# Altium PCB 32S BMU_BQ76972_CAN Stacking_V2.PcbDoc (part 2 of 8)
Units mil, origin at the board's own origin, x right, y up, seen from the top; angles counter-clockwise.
Board outline 7319.29 x 5216.54 mil, 4 copper layers (Top Layer, Layer 1, Layer 2, Bottom Layer), stack 73.068 mil thick; 811 components, 524 nets, 2320 pads, 2669 vias.
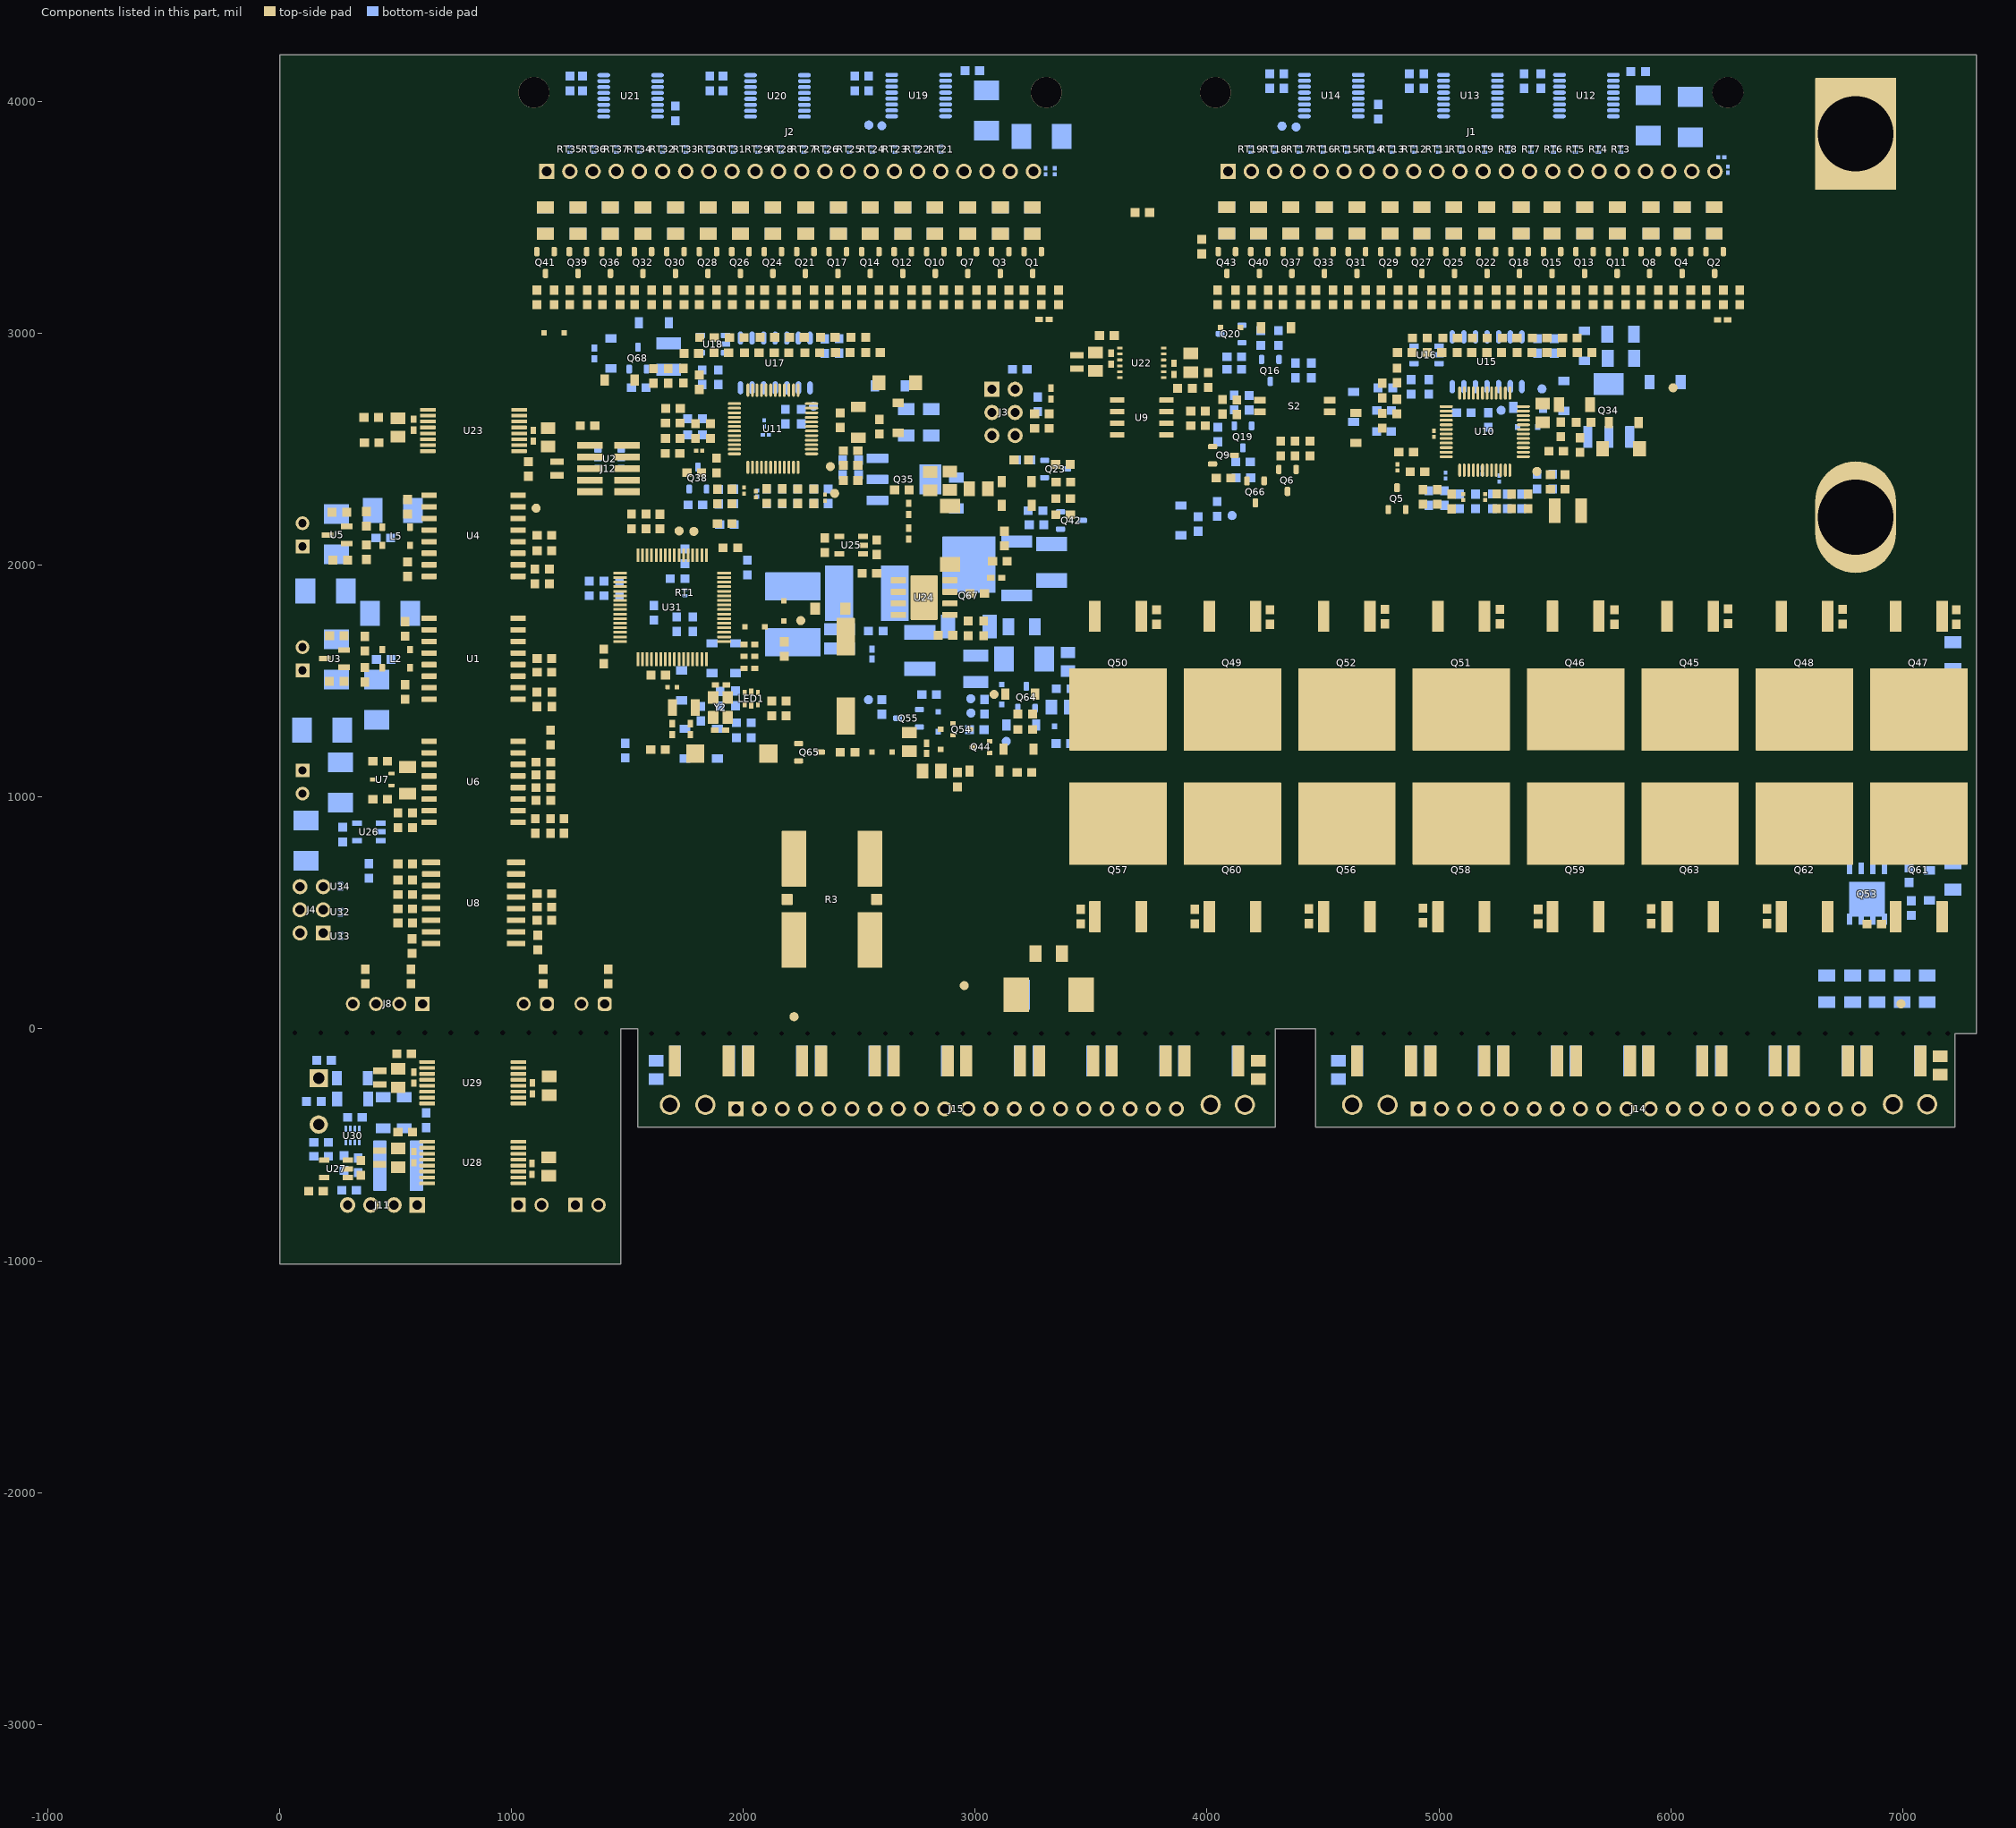
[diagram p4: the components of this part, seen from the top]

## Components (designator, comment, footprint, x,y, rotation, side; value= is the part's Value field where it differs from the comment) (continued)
R251 "CRCW0603100RFKEA" 0603 1695.4,2547.41 r0 top value=100
R252 "CRCW060310K0FKEA" 0603 2233.63,2298.04 r90 bottom value=10.0k
R253 "CRCW060310M0JNEA" 0603 3961.99,2178.07 r270 bottom value=10Meg
R254 "CRCW060310K0FKEA" 0603 1928.84,2175.36 r180 bottom value=10.0k
R255 "CRCW08051K50JNEA" 0805_HV 2812.37,1112.44 r0 top value=1.5k
R256 "CRCW06031M00JNEA" 0603 7027.93,663.39 r90 bottom value=1.0Meg
R257 "MCT06030C1004FP500" 0603 5107.86,2657.98 r0 bottom value=1.00Meg
R258 "RT0603BRD0749K9L" 0603 7037.77,521.14 r90 bottom value=49.9k
R259 "RC0603FR-07499RL" 0603 4044.23,2243.43 r270 bottom value=499
R260 "MCT06030C1004FP500" 0603 2249.69,2641.73 r90 bottom value=1.00Meg
R261 "CRCW0603806RFKEA" 0603 3215.59,1292.43 r180 top value=806
R262 "RC0603FR-07510RL" 0603 2597.25,1388.95 r270 bottom value=510
R263 "CRCW04020000Z0ED" 0603 3008.65,1878.64 r0 top value=0
R264 "CRCW04020000Z0ED" 0603 2683.68,2325.27 r180 top value=0
R265 "CRCW04020000Z0ED" 0603 394.83,2637.65 r180 top value=0
R266 "CRCW04020000Z0ED" 0603 384.71,681.15 r270 bottom value=0
R267 "CRCW04020000Z0ED" 0603 3904.87,2763.42 r0 top value=0
R268 "CRCW060375R0FKEA" 0603 4767.15,1778.76 r270 top value=75.0
R269 "CRCW060375R0FKEA" 0603 5915.35,486.14 r270 top value=75.0
R270 "CRCW060375R0FKEA" 0603 5262.84,1778.76 r270 top value=75.0
R271 "CRCW0603806RFKEA" 0603 2801.26,1442.73 r180 bottom value=806
R272 "CRCW080556K0JNEA" 0805_HV 2716.46,1238.36 r90 top value=56k
R273 "CRCW04020000Z0ED" 0603 3006.87,1290.78 r180 bottom value=0
R274 "CRCW080510R0FKEA" 0805_HV 3400.18,1583.79 r270 bottom value=10.0
R275 "CRCW0603806RFKEA" 0603 3040.45,1389.93 r90 bottom value=806
R276 "CRCW060375R0FKEA" 0603 6415.4,486.14 r270 top value=75.0
R277 "CRCW1206511RFKEA" 1206 6890.01,173.07 r270 bottom value=511
R278 "CRCW1206511RFKEA" 1206 7106.54,173.07 r270 bottom value=511
R279 "CRCW060375R0FKEA" 0603 3781.9,1776.95 r270 top value=75.0
R280 "CRCW060375R0FKEA" 0603 6878.09,452.83 r180 top value=75.0
R281 "CRCW060310M0JNEA" 0603 3380.2,1230.92 r180 bottom value=10Meg
R282 "CRCW060310M0JNEA" 0603 3381.89,1467.77 r180 bottom value=10Meg
R283 "CRCW080556K0JNEA" 0805_HV 3368.11,1388.43 r0 bottom value=56k
R284 "CRCW1206511RFKEA" 1206 6998.28,173.07 r270 bottom value=511
R285 "CRCW1206511RFKEA" 1206 6784.57,173.07 r270 bottom value=511
R286 "CRCW1206511RFKEA" 1206 6673.47,173.07 r270 bottom value=511
R287 "CRCW060375R0FKEA" 0603 4271.89,1776.95 r270 top value=75.0
R288 "CRCW060375R0FKEA" 0603 3946.85,484.33 r270 top value=75.0
R289 "CRCW060375R0FKEA" 0603 6742.13,1778.27 r270 top value=75.0
R290 "CRCW060375R0FKEA" 0603 5428.59,484.33 r270 top value=75.0
R291 "CRCW060375R0FKEA" 0603 7231.5,1776.95 r270 top value=75.0
R292 "CRCW0603100RFKEA" 0603 2449.45,1193.85 r0 top value=100
R293 "RC0603FR-0720RL" 0603 2176.72,1638.46 r270 top value=20.0
R294 "CRCW060310M0JNEA" 0603 2122.27,1382.74 r90 top value=10Meg
R295 "CRCW04020000Z0ED" 0603 1706.98,3949.41 r90 bottom value=0
R296 "CRCW04020000Z0ED" 0603 4737.95,3956.69 r90 bottom value=0
R297 "CRCW060310M0JNEA" 0603 1793.08,2260.63 r0 bottom value=10Meg
R298 "CRCW04020000Z0ED" 0603 2181,2641.73 r90 bottom value=0
R299 "CRCW06035K10JNEA" 0603 1966.1,1426 r270 bottom value=5.1k
R300 "RC0603FR-07604KL" 0603 2001.98,1320.58 r0 bottom value=604k
R301 "CRCW04020000Z0ED" 0603 5213,2626.49 r90 bottom value=0
R302 "RC0603FR-07620KL" 0603 1899.4,1424.64 r270 bottom value=620k
R303 "CRCW060310M0JNEA" 0603 3212.44,1106.53 r0 top value=10Meg
R304 "CRCW060310M0JNEA" 0603 3215.59,1358.27 r0 top value=10Meg
R305 "CRCW0603100RFKEA" 0603 1328.1,2601.68 r0 top value=100
R306 "CRCW06035K10JNEA" 0603 1816.22,1360.22 r270 bottom value=5.1k
R307 "CRCW06035K10JNEA" 0603 2001.98,1256.53 r0 bottom value=5.1k
R308 "CRM2512-FX-2000ELF" 2512 3179.09,1985.78 r90 bottom value=200
R309 "RC1206FR-0720KL" 1206 3200.19,1735.24 r180 bottom value=20.0k
R310 "CRCW060318K2FKEA" 0603 1072.66,2415.93 r90 top value=18.2k
R311 "CRCW060318K2FKEA" 0603 3567.95,2991.26 r0 top value=18.2k
R312 "CRCW060375R0FKEA" 0603 4931.1,489.33 r270 top value=75.0
R313 "CRCW060375R0FKEA" 0603 5757.22,1776.95 r270 top value=75.0
R314 "CRCW060375R0FKEA" 0603 3454.88,484.33 r270 top value=75.0
R315 "CRCW04020000Z0ED" 0603 191.22,-135.3 r0 bottom value=0
R316 "CRCW060375R0FKEA" 0603 6247.93,1780.08 r270 top value=75.0
R317 "RC0603FR-07499KL" 0603 3106.22,2018.01 r180 top value=499k
R318 "CRCW04020000Z0ED" 0603 338.47,-588.05 r270 bottom value=0
R319 "CRCW04020000Z0ED" 0603 147.11,-312.46 r0 bottom value=0
R320 "CRCW0402523KFKED" 0402 2713.67,2136.82 r90 top value=523k
R321 "CRCW060375R0FKEA" 0603 4438.98,486.14 r270 top value=75.0
R322 "CRCW060318K2FKEA" 0603 541.48,-444.84 r0 top value=18.2k
R323 "CRCW060318K2FKEA" 0603 536.9,-107.1 r0 top value=18.2k
R324 "CRCW0603200KFKEA" 0603 3036.59,1728.11 r90 top value=200k
R325 "CRCW060382K5FKEA" 0603 2571.25,1716.54 r180 bottom value=82.5k
R326 "RC0603FR-0710K2L" 0603 178.6,-489.24 r0 bottom value=10.2k
R327 "RC0603FR-0753K6L" 0603 178.6,-548.68 r0 bottom value=53.6k
R328 "CRCW060363K4FKEA" 0603 2871.53,1698 r0 top value=63.4k
R329 "CRCW060310K0FKEA" 0603 2923.23,1075.04 r90 top value=10.0k
R330 "RT0603BRD0718KL" 0603 2987.63,4133.51 r0 bottom value=18.0k
R331 "CRCW2512200RFKEG" 2512 4764.51,-137.67 r180 bottom value=200
R332 "CRCW2512200RFKEG" 2512 4763.1,-137.67 r180 top value=200
R333 "CRCW2512200RFKEG" 2512 5078.06,-137.67 r180 bottom value=200
R334 "CRCW2512200RFKEG" 2512 5080.3,-137.67 r180 top value=200
R335 "CRCW2512200RFKEG" 2512 5391.62,-137.67 r180 bottom value=200
R336 "CRCW2512200RFKEG" 2512 5394.68,-137.67 r180 top value=200
R337 "CRCW2512200RFKEG" 2512 5705.17,-137.67 r180 bottom value=200
R338 "CRCW2512200RFKEG" 2512 5708.44,-137.67 r180 top value=200
R339 "CRCW2512200RFKEG" 2512 6018.72,-137.67 r180 bottom value=200
R340 "CRCW2512200RFKEG" 2512 6020.32,-137.67 r180 top value=200
R341 "CRCW2512200RFKEG" 2512 6332.28,-137.67 r180 bottom value=200
R342 "CRCW2512200RFKEG" 2512 6335.48,-137.67 r180 top value=200
R343 "CRCW2512200RFKEG" 2512 6645.83,-137.67 r180 bottom value=200
R344 "CRCW2512200RFKEG" 2512 6648.16,-137.67 r180 top value=200
R345 "CRCW2512200RFKEG" 2512 6959.39,-137.67 r180 bottom value=200
R346 "CRCW2512200RFKEG" 2512 6961.57,-137.67 r180 top value=200
R347 "CRCW080510R0FKEA" 0805_HV 4566.78,-177.03 r270 bottom value=10.0
R348 "CRCW080510R0FKEA" 0805_HV 7162.65,-157.32 r270 top value=10.0
R349 "CRCW2512200RFKEG" 2512 1821.74,-137.66 r180 bottom value=200
R350 "CRCW2512200RFKEG" 2512 1820.33,-137.66 r180 top value=200
R351 "CRCW2512200RFKEG" 2512 2135.3,-137.66 r180 bottom value=200
R352 "CRCW2512200RFKEG" 2512 2137.53,-137.66 r180 top value=200
R353 "CRCW2512200RFKEG" 2512 2448.85,-137.66 r180 bottom value=200
R354 "CRCW2512200RFKEG" 2512 2451.92,-137.66 r180 top value=200
R355 "CRCW2512200RFKEG" 2512 2762.41,-137.66 r180 bottom value=200
R356 "CRCW2512200RFKEG" 2512 2765.67,-137.67 r180 top value=200
R357 "CRCW2512200RFKEG" 2512 3075.96,-137.66 r180 bottom value=200
R358 "CRCW2512200RFKEG" 2512 3077.55,-137.67 r180 top value=200
R359 "CRCW2512200RFKEG" 2512 3389.51,-137.66 r180 bottom value=200
R360 "CRCW2512200RFKEG" 2512 3392.71,-137.67 r180 top value=200
R361 "CRCW2512200RFKEG" 2512 3703.07,-137.66 r180 bottom value=200
R362 "CRCW2512200RFKEG" 2512 3705.39,-137.67 r180 top value=200
R363 "CRCW2512200RFKEG" 2512 4016.62,-137.66 r180 bottom value=200
R364 "CRCW2512200RFKEG" 2512 4018.8,-137.67 r180 top value=200
R365 "CRCW080510R0FKEA" 0805_HV 1624.02,-177.03 r270 bottom value=10.0
R366 "CRCW080510R0FKEA" 0805_HV 4221.47,-177.03 r270 top value=10.0
RT1 "TMP6131DECR" DEC0002A 1747.87,1882.35 r90 bottom
RT3 "TMP6131DECR" DEC0002A 5784.71,3794.29 r90 bottom
RT4 "TMP6131DECR" DEC0002A 5687.79,3794.29 r90 bottom
RT5 "TMP6131DECR" DEC0002A 5588.75,3794.29 r90 bottom
RT6 "TMP6131DECR" DEC0002A 5494.58,3794.29 r90 bottom
RT7 "TMP6131DECR" DEC0002A 5397.64,3794.29 r90 bottom
RT8 "TMP6131DECR" DEC0002A 5297.64,3794.29 r90 bottom
RT9 "TMP6131DECR" DEC0002A 5197.64,3794.29 r90 bottom
RT10 "TMP6131DECR" DEC0002A 5097.07,3794.29 r90 bottom
RT11 "TMP6131DECR" DEC0002A 4997.64,3794.29 r90 bottom
RT12 "TMP6131DECR" DEC0002A 4894.04,3794.29 r90 bottom
RT13 "TMP6131DECR" DEC0002A 4797.64,3794.29 r90 bottom
RT14 "TMP6131DECR" DEC0002A 4706.95,3794.29 r90 bottom
RT15 "TMP6131DECR" DEC0002A 4603.33,3794.29 r90 bottom
RT16 "TMP6131DECR" DEC0002A 4499.71,3794.29 r90 bottom
RT17 "TMP6131DECR" DEC0002A 4396.09,3794.29 r90 bottom
RT18 "TMP6131DECR" DEC0002A 4292.46,3794.29 r90 bottom
RT19 "TMP6131DECR" DEC0002A 4188.84,3794.29 r90 bottom
RT21 "TMP6131DECR" DEC0002A 2852.05,3794.66 r90 bottom
RT22 "TMP6131DECR" DEC0002A 2751.62,3794.29 r90 bottom
RT23 "TMP6131DECR" DEC0002A 2653.94,3794.29 r90 bottom
RT24 "TMP6131DECR" DEC0002A 2555.91,3794.29 r90 bottom
RT25 "TMP6131DECR" DEC0002A 2457.49,3794.29 r90 bottom
RT26 "TMP6131DECR" DEC0002A 2359.06,3794.29 r90 bottom
RT27 "TMP6131DECR" DEC0002A 2260.63,3794.29 r90 bottom
RT28 "TMP6131DECR" DEC0002A 2162.42,3794.29 r90 bottom
RT29 "TMP6131DECR" DEC0002A 2062.29,3794.29 r90 bottom
RT30 "TMP6131DECR" DEC0002A 1857.09,3794.29 r90 bottom
RT31 "TMP6131DECR" DEC0002A 1955.52,3794.29 r90 bottom
RT32 "TMP6131DECR" DEC0002A 1651.43,3794.29 r90 bottom
RT33 "TMP6131DECR" DEC0002A 1751.43,3794.29 r90 bottom
RT34 "TMP6131DECR" DEC0002A 1551.97,3794.29 r90 bottom
RT35 "TMP6131DECR" DEC0002A 1251.43,3794.29 r90 bottom
RT36 "TMP6131DECR" DEC0002A 1355.12,3794.29 r90 bottom
RT37 "TMP6131DECR" DEC0002A 1452.64,3794.29 r90 bottom
S1 "RS-032G05A3-SM RT" SW_RS-032G05A3-SM 1950.18,1187.94 r180 top
S2 "416131160802" SW_416131160802 4378.39,2687.15 r0 top
TP1 "" TP_SM_1MM 2597.27,3895.98 r90 bottom
TP2 "" TP_SM_1MM 6010.32,2765.51 r90 top
TP3 "" TP_SM_1MM 1722.95,2148.31 r90 top
TP4 "" TP_SM_1MM 1106.07,2246.34 r90 top
TP5 "" TP_SM_1MM 6993.21,108.27 r90 top
TP6 "" TP_SM_1MM 2952.76,187.01 r90 top
TP7 "" TP_SM_1MM 4107.9,2214.69 r90 bottom
TP8 "" TP_SM_1MM 1786.34,2146.12 r90 top
TP9 "I-" Keystone5009 4779.08,-327.36 r180 top
TP10 "" TP_SM_1MM 2980.84,1424.5 r90 bottom
TP11 "" TP_SM_1MM 2981.8,1362.7 r90 bottom
TP12 "I-" Keystone5009 6958.59,-324.8 r180 top
TP13 "" TP_SM_1MM 2247.37,1761.57 r90 top
TP14 "" TP_SM_1MM 2218.5,52.75 r90 top
TP15 "" TP_SM_1MM 2540.79,3899.06 r90 bottom
TP16 "" TP_SM_1MM 4323.5,3894.63 r90 bottom
TP17 "BAT-" Keystone5011 4625.84,-327.36 r270 top
TP18 "" TP_SM_1MM 4384.07,3890.72 r90 bottom
TP21 "" TP_SM_1MM 2302.43,2686.17 r90 bottom
TP22 "" TP_SM_1MM 5268.67,2668.29 r90 bottom
TP23 "" TP_SM_1MM 2375.35,2426.02 r90 top
TP24 "BAT+" Keystone5010 7106.54,-324.8 r180 top
TP25 "I-" Keystone5009 1836.32,-327.35 r180 top
TP25 "" TP_SM_1MM 2393.81,2310.15 r90 top
TP26 "" TP_SM_1MM 5423.12,2404.8 r90 top
TP27 "I-" Keystone5009 4015.75,-327.36 r180 top
TP28 "BAT-" Keystone5011 1683.07,-327.35 r270 top
TP29 "BAT+" Keystone5010 4163.39,-327.36 r180 top
TP30 "DSG_GATE" TP_SM_1MM 3081.52,1443.11 r90 top
U1 "ISO1042DWR" DW0016B_HV 836.48,1596.63 r180 top
U2 "TPD4E001DBVR" DBV0006A_L 1422.76,2459.36 r180 bottom
U3 "ESD2CAN24DBZR" DBZ0003A-MFG 236.33,1597.49 r180 top
U4 "ISO1042DWR" DW0016B_HV 836.48,2127.08 r180 top
U5 "ESD2CAN24DBZR" DBZ0003A-MFG 247.93,2130.67 r180 top
U6 "ISO1410DWR" DW0016B_HV 836.48,1066.17 r180 top
U7 "TPD2E007DCKR" DCK0003A_L 442.04,1075.84 r180 top
U8 "ISO6731DWR" DW0016A-MFG 836.48,543.59 r180 top
U9 "ISO1640BDR" D0008A-MFG 3718.6,2637.79 r0 top
U10 "bq76952PFBR" PFB0048A_N 5198.01,2576.53 r270 top
U11 "bq76952PFBR" PFB0048A_N 2127.64,2589.03 r270 top
U12 "SN74LV4052APWR" PW0016A_N 5636.31,4026.18 r180 bottom
U13 "SN74LV4052APWR" PW0016A_N 5136.26,4026.18 r180 bottom
U14 "SN74LV4052APWR" PW0016A_N 4536.21,4026.18 r180 bottom
U15 "SN74HCS74DR" D0014A_N 5207.86,2877.95 r90 bottom
U16 "SN74AUC1G86DBVR" DBV0005A_N 4946.86,2907.48 r180 bottom
U17 "SN74HCS74DR" D0014A_N 2137.48,2872.83 r90 bottom
U18 "SN74AUC1G86DBVR" DBV0005A_N 1868.74,2954.17 r180 bottom
U19 "SN74LV4052APWR" PW0016A_N 2756.18,4026.18 r180 bottom
U20 "SN74LV4052APWR" PW0016A_N 2146.99,4024.61 r180 bottom
U21 "SN74LV4052APWR" PW0016A_N 1513.78,4024.61 r180 bottom
U22 "UCC33410" RAQ0012B-MFG 3718.05,2873.03 r0 top
U23 "UCC33421-Q1" DWX0016A-MFG 836.04,2581.74 r180 top
U24 "LM5168PDDAR" DDA0008E_M 2779.61,1860.41 r0 top
U25 "TPS7A2433DBVR" DBV0005A-MFG 2464.64,2086.68 r180 top
U26 "TPS7A2433DBVR" DBV0005A-MFG 384.71,850.3 r180 bottom
U27 "TPS7A2433DBVR" DBV0005A-MFG 243.03,-603.51 r180 top
U28 "UCC33421-Q1" DWX0016A-MFG 833.07,-576.64 r0 top
U29 "UCC33421-Q1" DWX0016A-MFG 833.07,-232.15 r0 top
U30 "TPS62932DRLR" DRL0008A-MFG 314.43,-460.1 r270 bottom
U31 "MSPM0G3519SPM" PM0064A-MFG 1692.78,1819.1 r270 top
U32 "TPD1E10B06DPYR" DPY0002A 261.69,503.84 r90 bottom
U33 "TPD1E10B06DPYR" DPY0002A 261.69,400.89 r90 bottom
U34 "TPD1E10B06DPYR" DPY0002A 261.69,615.06 r270 bottom
Y1 "X1A0001410014" Epson_FC-135 1742.81,1386.86 r180 top
Y2 "X1E0000210179" FP-X1E0000210179_TSX-3225-MFG 1900.78,1386.86 r270 top
ZZ1 "These assemblies are ESD sensitive, ESD precautions shall be observed." AssemblyNote 7857.59,769.14 r90 top
ZZ2 "These assemblies must be clean and free from flux and all contaminants. Use of no clean flux is not acceptable." AssemblyNote 7621.37,-785.97 r90 top
ZZ3 "These assemblies must comply with workmanship standards IPC-A-610 Class 2, unless otherwise specified." AssemblyNote 7385.15,-451.33 r90 top

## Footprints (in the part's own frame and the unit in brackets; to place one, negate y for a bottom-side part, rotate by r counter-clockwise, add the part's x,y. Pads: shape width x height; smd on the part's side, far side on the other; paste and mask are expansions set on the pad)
19-337_RGB [mm] "SMD, 6-Leads, Body 1.6x1.6mm"
  rect 0.55x0.4 smd: 1(-0.675,0.725) 3(-0.675,-0.725) 4(0.675,0.725) 6(0.675,-0.725)
  rect 0.7x0.5 smd: 2(-0.75,0) 5(0.75,0)
  silkscreen extent -1.2,0.6 -1.2,0.9, body extent -0.85,-0.85 0.85,0.85, height 0.35
0201 [mm] "Data from Kemet datasheet CC101_COM dated 7/28/11"
  rect 0.46x0.42 smd mask+0.048: 1(-0.33,0) 2(0.33,0)
  body extent -0.31,-0.16 0.31,0.16, height 0.26
0402 [mm] "0402 from SM-752 data"
  rect 0.8x0.6 smd: 1(-0.6,0) 2(0.6,0)
  silkscreen extent -1.22,-0.52 1.22,0.52, body extent -0.55,-0.3 0.55,0.3, height 0.6
0603 [mm] "0603 from SM-752 data"
  rect 1x0.95 smd: 1(-0.8,0) 2(0.8,0)
  silkscreen extent -1.52,-0.69 1.52,0.69, body extent -0.87,-0.47 0.87,0.47, height 1
0805_HV [mil] "0805 with 30mil clearance between pads"
  rect 50x63 smd: 1(-40,0) 2(40,0)
  silkscreen extent -74,-40 74,40, body extent -43,-29 43,29, height 57
1206 [mm] "1206 from SM-752 data"
  rect 1.3x1.85 smd: 1(-1.45,0) 2(1.45,0)
  silkscreen extent -2.4,-1.21 2.4,1.21, body extent -1.7,-0.9 1.7,0.9, height 1.35
1206_180 [mm] "1206_180"
  rect 1.1x1.6 smd: 1(-1.7,0) 2(1.7,0)
  silkscreen extent -0.9,-1 0.9,1, body extent -1.75,-0.95 1.75,0.95, height 1.8
1206_190 [mm] "1206_190"
  rect 1.1x1.6 smd: 1(-1.7,0) 2(1.7,0)
  silkscreen extent -0.9,-1 0.9,1, body extent -1.75,-0.95 1.75,0.95, height 1.9
1210 [mm] "1210 from SM-752 data"
  rect 1.3x2.7 smd: 1(-1.45,0) 2(1.45,0)
  silkscreen extent -2.32,-1.57 2.32,1.57, body extent -1.7,-1.35 1.7,1.35, height 1.35
1812_280 [mm] "1812"
  rect 1.6x3.4 smd: 1(-2,0) 2(2,0)
  silkscreen extent -0.8,-1.6 0.8,1.6, body extent -2.4,-1.7 2.4,1.7, height 2.8
2220_450 [mm] "Laird recommended land pattern"
  rrect3% 3.07x6.1 smd: 1(-3.06,0) 2(3.06,0)
  silkscreen extent -1.3,-3 1.3,3, body extent -2.8,-2.54 2.79,2.54, height 4.5
2512 [mm] "Chip Resistor, Body 6.3x3.2mm, IPC Medium Density"
  rect 1.3x3.4 smd: 1(-2.95,0) 2(2.95,0)
  silkscreen extent -1.9,-1.6 1.9,1.6, body extent -3.22,-1.67 3.22,1.67, height 0.71
AssemblyNote [mil] "Assembly Note"
CE_Mark_5mm [mil] "Minimum text height for CE Mark"
  silkscreen extent -138,-98 138,98
D0008A-MFG [mm]
  rrect17% 1.55x0.6 smd paste+0 mask+0: 1(-2.7,1.905) 2(-2.7,0.635) 3(-2.7,-0.635) 4(-2.7,-1.905) 5(2.7,-1.905) 6(2.7,-0.635) 7(2.7,0.635) 8(2.7,1.905)
  silkscreen extent -4.17,-2.5 1.5,2.5, body extent -3.57,-2.75 3.57,2.75, height 0.25
D0014A_N [mm] "SOIC, 14-Leads, Body 8.7x3.9mm, Pitch 1.27mm, IPC Medium Density"
  oval 1.45x0.6 smd: 1(-2.725,3.81) 2(-2.725,2.54) 3(-2.725,1.27) 4(-2.725,0) 5(-2.725,-1.27) 6(-2.725,-2.54) 7(-2.725,-3.81) 8(2.725,-3.81) 9(2.725,-2.54) 10(2.725,-1.27) 11(2.725,0) 12(2.725,1.27) 13(2.725,2.54) 14(2.725,3.81)
  silkscreen extent -3.3,-4.4 0.9,4.4, body extent -3.02,-4.32 3.02,4.32, height 1.6
DBV0005A-MFG [mm]
  rrect17% 1.1x0.6 smd paste+0 mask+0: 1(-1.3,0.95) 2(-1.3,0) 3(-1.3,-0.95) 4(1.3,-0.95) 5(1.3,0.95)
  silkscreen extent -2.58,-1.53 0.87,1.53, body extent -1.95,-1.78 1.95,1.78, height 0.25
DBV0005A_N [mm] "SOT23, 5-Leads, Body 2.9x1.6mm, Pitch 0.95mm, Lead Span 2.8mm, IPC Medium Density"
  rrect17% 1x0.6 smd: 1(-1.375,0.95) 2(-1.375,0) 3(-1.375,-0.95) 4(1.375,-0.95) 5(1.375,0.95)
  silkscreen extent -1.63,-1.55 0.38,1.55, body extent -1.42,-1.46 1.42,1.46, height 1.09
DBV0006A_L [mm] "SOT23, 6-Leads, Body 2.9x1.6mm, Pitch 0.95mm, Lead Span 2.8mm, IPC High Density"
  rrect18% 0.8x0.55 smd: 1(-1.275,0.95) 2(-1.275,0) 3(-1.275,-0.95) 4(1.275,-0.95) 5(1.275,0) 6(1.275,0.95)
  silkscreen extent -1.55,-1.53 0.55,1.53, body extent -1.42,-1.46 1.42,1.46, height 1.12
DBZ0003A-MFG [mm]
  rrect17% 1.3x0.6 smd paste+0 mask+0: 1(-1.05,0.95) 2(-1.05,-0.95) 3(1.05,0)
  silkscreen extent -0.7,-1.52 0.7,1.52, body extent -1.8,-1.62 1.8,1.62, height 0.25
DCK0003A_L [mm] "SOT23, 3-Leads, Body 2.0x1.25mm, Pitch 0.65mm, Lead Span 2.1mm, IPC High Density"
  rrect25% 0.65x0.4 smd: 1(-1.025,0.65) 2(-1.025,-0.65) 3(1.025,0)
  silkscreen extent -0.97,-1.1 0.7,1.52, body extent -1.06,-1 1.06,1, height 1.1
DDA0008E_M [mm]
  rrect15% 1.65x0.65 smd: 1(-2.825,1.905) 2(-2.825,0.635) 3(-2.825,-0.635) 4(-2.825,-1.905) 5(2.825,-1.905) 6(2.825,-0.635) 7(2.825,0.635) 8(2.825,1.905)
  rrect7% 2.95x4.9 smd paste-1.5 mask-1.5: 9(0,0)
  rrect4% 2.4x3.1 on Top Paste: 9(0,0)
  rrect4% 2.4x3.1 on Top Solder: 9(0,0)
  silkscreen extent -3.42,-2.52 1.4,2.5, body extent -3,-2.45 3,2.45, height 1.57
DDPAK [mil] "D2-PAK, 3-Pads, Body 9.7x10.4mm (max), TO-263AB, using Vishay Silionix recommended pad sizes"
  rrect8% 135x49.49 smd: 1(-246.06,100) 3(-246.06,-100)
  rrect1% 355x420 smd paste-181.1: 4(155.51,0)
  silkscreen extent -295,-220 344,220, body extent -295,-202 324,202, height 180
DEC0002A [mm] "X1SON-2"
  rrect57% 0.35x0.6 smd paste-0.5 mask-0.05: 1(-0.325,0) 2(0.325,0)
  rrect33% 0.3x0.5 on Bottom Paste: 1S(-0.35,0) 2S(0.35,0)
  body extent -0.5,-0.3 0.5,0.3, height 0.5
DPAK [mm] "D-PAK, 3-Pads, Body 6.22x6.73mm (max), TO-252AA using nominal STEP model"
  rrect6% 2.6x1.6 smd: 1(-3.4,2.28) 3(-3.4,-2.28)
  rrect2% 6.2x5.8 smd paste-2.9: 4(3.4,0)
  silkscreen extent -4.5,-3.3 4.7,3.28, body extent -3.86,-3.29 5.84,3.29, height 2.48
DPY0002A [mm] "X1SON-2"
  rrect57% 0.35x0.6 smd paste-0.5 mask-0.05: 1(-0.325,0) 2(0.325,0)
  rrect33% 0.3x0.5 on Bottom Paste: 1S(-0.35,0) 2S(0.35,0)
  silkscreen extent -0.85,-0.02 -0.8,0.03, body extent -0.5,-0.3 0.5,0.3, height 0.45
DRL0008A-MFG [mm]
  rrect33% 0.67x0.3 smd paste+0 mask+0: 1(-0.74,0.75) 2(-0.74,0.25) 3(-0.74,-0.25) 4(-0.74,-0.75) 5(0.74,-0.75) 6(0.74,-0.25) 7(0.74,0.25) 8(0.74,0.75)
  silkscreen extent -1.77,-1.28 0.65,1.28, body extent -0.8,-1.05 0.8,1.05, height 0.6
DW0016A-MFG [mm]
  rrect17% 2x0.6 smd paste+0 mask+0: 1(-4.65,4.445) 2(-4.65,3.175) 3(-4.65,1.905) 4(-4.65,0.635) 5(-4.65,-0.635) 6(-4.65,-1.905) 7(-4.65,-3.175) 8(-4.65,-4.445) 9(4.65,-4.445) 10(4.65,-3.175) 11(4.65,-1.905) 12(4.65,-0.635) 13(4.65,0.635) 14(4.65,1.905) 15(4.65,3.175) 16(4.65,4.445)
  silkscreen extent -6.33,-5.25 3.15,5.25, body extent -5.75,-5.35 5.75,5.35, height 0.25
DW0016B_HV [mm] "SOIC-16, HV/isolation option"
  rrect17% 1.65x0.6 smd: 1(-4.875,4.445) 2(-4.875,3.175) 3(-4.875,1.905) 4(-4.875,0.635) 5(-4.875,-0.635) 6(-4.875,-1.905) 7(-4.875,-3.175) 8(-4.875,-4.445) 9(4.875,-4.445) 10(4.875,-3.175) 11(4.875,-1.905) 12(4.875,-0.635) 13(4.875,0.635) 14(4.875,1.905) 15(4.875,3.175) 16(4.875,4.445)
  body extent -5.17,-5.15 5.17,5.15, height 2.59
DWX0016A-MFG [mm]
  rrect24% 1.7x0.41 smd paste+0 mask+0: 1(-5,2.275) 2(-5,1.625) 3(-5,0.975) 4(-5,0.325) 5(-5,-0.325) 6(-5,-0.975) 7(-5,-1.625) 8(-5,-2.275) 9(5,-2.275) 10(5,-1.625) 11(5,-0.975) 12(5,-0.325) 13(5,0.325) 14(5,0.975) 15(5,1.625) 16(5,2.275)
  silkscreen extent -6.53,-2.98 3.8,2.98, body extent -5.95,-3.22 5.95,3.22, height 0.25
Epson_FC-135 [mm] "SMD, 2-Leads, Body 3.2x1.5mm"
  rect 1x1.8 smd: 1(-1.25,0) 2(1.25,0)
  silkscreen extent -0.35,-0.8 0.35,0.8, body extent -1.65,-0.8 1.65,0.8, height 0.9
FCC_disclaimer [mil]
FP-705550056_HDR22-MFG [mm]
  rrect6% 1.69x1.69 hole 1.09 paste-1000 mask+0: 1(26.67,6.145)
  round 1.69 hole 1.09 paste-1000 mask+0: 2(24.13,6.145) 3(21.59,6.145) 4(19.05,6.145) 5(16.51,6.145) 6(13.97,6.145) 7(11.43,6.145) 8(8.89,6.145) 9(6.35,6.145) 10(3.81,6.145) 11(1.27,6.145) 12(-1.27,6.145) 13(-3.81,6.145) 14(-6.35,6.145) 15(-8.89,6.145) 16(-11.43,6.145) 17(-13.97,6.145) 18(-16.51,6.145) 19(-19.05,6.145) 20(-21.59,6.145) 21(-24.13,6.145) 22(-26.67,6.145)
  round 3.4 hole 3.4 unplated paste-1000 mask+0: ""(-28.07,-2.495) ""(28.07,-2.495)
  body extent -30.18,-7.04 30.18,7.09, height 0.25
FP-CGA5H2X8R2A104K115AA_1206-MFG [mm]
  rrect9% 1.1x1.35 smd paste+0 mask+0: 1(-1.65,0) 2(1.65,0)
  body extent -2.3,-1 2.3,1, height 0.25
FP-EEV-EB2C100Q_RADIAL-MFG [mm]
  rrect5% 4.1x2 smd paste+0 mask+0: 1(-4.35,0) 2(4.35,0)
  silkscreen extent -7.07,-5.25 5.25,5.25, body extent -6.65,-5.5 6.65,5.5, height 0.25
FP-ERA-2AEB104X_0402-MFG [mm]
  rrect21% 0.475x0.5 smd paste+0 mask+0: 1(-0.512,0) 2(0.512,0)
  silkscreen extent -0.5,-0.63 0.5,0.63, body extent -0.85,-0.4 0.85,0.4, height 0.25
FP-PF-MB1-150_BT_FUSE_56MM0_17MM4-MFG [mm]
  rrect1% 12.25x8.85 hole 8.25 slot 11.65 at 0 deg paste-1000 mask+0: 1(-21,0)
  rrect100% 12.25x8.85 hole 8.25 slot 11.65 at 0 deg paste-1000 mask+0: 2(21,0)
  silkscreen extent -14.6,-8.85 14.6,8.85, body extent -27.23,-8.95 27.23,8.95, height 0.25
FP-PPTC021LGBN-RC_CONN_HDR2-MFG [mm]
  rrect6% 1.57x1.57 hole 1.02 paste-1000 mask+0: 1(-1.27,5.85)
  round 1.57 hole 1.02 paste-1000 mask+0: 2(1.27,5.85)
  silkscreen extent -2.97,-4.4 2.97,5.97, body extent -3.07,-4.5 3.07,6.74, height 0.25
FP-SEWF3951FL300PT_3951-MFG [mm]
  rrect4% 2.7x6.1 smd paste+0 mask+0: 1(-4.15,-4.45) 1(-4.15,4.45) 2(4.15,-4.45) 2(4.15,4.45)
  rrect8% 1.2x1.2 smd paste+0 mask+0: 3(-4.9,0) 4(4.9,0)
  silkscreen extent -6.17,-6.75 2.42,6.75, body extent -5,-6.5 5,6.5, height 2.6
FP-SMDJ54CA_DO-214AB-MFG [mm]
  rrect4% 2.4x3.3 smd paste+0 mask+0: 1(-3.3,0) 2(3.3,0)
  silkscreen extent -3.55,-3.11 3.55,3.11, body extent -3.97,-2.95 3.97,2.95, height 2.62
FP-SRF3225TAC-510Y_SMT4-MFG [mm]
  rrect15% 0.65x0.8 smd paste+0 mask+0: 1(-1.525,-1) 2(1.525,-1) 3(1.525,1) 4(-1.525,1)
  silkscreen extent -2.53,-1.35 1.7,1.35, body extent -1.95,-1.5 1.95,1.5, height 0.25
FP-X1E0000210179_TSX-3225-MFG [mm]
  rrect9% 1.4x1.15 smd paste+0 mask+0: 1(-1.1,-0.8) 2(1.1,-0.8) 3(1.1,0.8) 4(-1.1,0.8)
  silkscreen extent -1.22,-2.05 0,1.33, body extent -1.9,-1.48 1.9,1.48, height 0.25
HDR1X2 [mm] "Connector; Header; 2 Position"
  rect 1.5x1.5 hole 0.9: 1(0,0)
  round 1.5 hole 0.9: 2(2.54,0)
  silkscreen extent -1.27,-1.27 3.81,1.27
IEC_HighVoltage_Small [mil]
  silkscreen extent -107,-88 107,97
Keystone5009 [mil] "Keystone Compact loops"
  round 87 hole 63: 1(0,0)
  silkscreen extent -70,-70 70,70, body extent -63,-63 62,62, height 225
Keystone5010 [mil] "Keystone Multipurpose loops"
  round 87 hole 63: 1(0,0)
  silkscreen extent -70,-70 70,70, body extent -63,-63 63,62, height 319
Keystone5011 [mil] "Keystone Multipurpose loops"
  round 87 hole 63: 1(0,0)
  silkscreen extent -70,-70 70,70, body extent -63,-63 63,62, height 319
On-Shore_ED120_2DS [mm] "ONSHORE"
  rrect5% 2x2 hole 1.25: 1(-2.54,0)
  round 2 hole 1.25: 2(2.54,0)
  silkscreen extent -5.6,-4 5.12,5, body extent -5.78,-4 5.08,5, height 13
PFB0048A_N [mm] "Thin QFP, 48-Leads, Body 7x7mm, Pitch 0.5mm, IPC Medium Density"
  oval 1.45x0.3 smd: 1(-4.225,2.75) 2(-4.225,2.25) 3(-4.225,1.75) 4(-4.225,1.25) 5(-4.225,0.75) 6(-4.225,0.25) 7(-4.225,-0.25) 8(-4.225,-0.75) 9(-4.225,-1.25) 10(-4.225,-1.75) 11(-4.225,-2.25) 12(-4.225,-2.75) 25(4.225,-2.75) 26(4.225,-2.25) 27(4.225,-1.75) 28(4.225,-1.25) 29(4.225,-0.75) 30(4.225,-0.25) 31(4.225,0.25) 32(4.225,0.75) 33(4.225,1.25) 34(4.225,1.75) 35(4.225,2.25) 36(4.225,2.75)
  oval 0.3x1.45 smd: 13(-2.75,-4.225) 14(-2.25,-4.225) 15(-1.75,-4.225) 16(-1.25,-4.225) 17(-0.75,-4.225) 18(-0.25,-4.225) 19(0.25,-4.225) 20(0.75,-4.225) 21(1.25,-4.225) 22(1.75,-4.225) 23(2.25,-4.225) 24(2.75,-4.225) 37(2.75,4.225) 38(2.25,4.225) 39(1.75,4.225) 40(1.25,4.225) 41(0.75,4.225) 42(0.25,4.225) 43(-0.25,4.225) 44(-0.75,4.225) 45(-1.25,4.225) 46(-1.75,4.225) 47(-2.25,4.225) 48(-2.75,4.225)
  silkscreen extent -4.17,-2.75 2.75,3.58, body extent -4.5,-4.5 4.5,4.5, height 1.07
PM0064A-MFG [mm]
  rrect33% 1.5x0.3 smd paste+0 mask+0: 1(-5.7,3.75) 2(-5.7,3.25) 3(-5.7,2.75) 4(-5.7,2.25) 5(-5.7,1.75) 6(-5.7,1.25) 7(-5.7,0.75) 8(-5.7,0.25) 9(-5.7,-0.25) 10(-5.7,-0.75) 11(-5.7,-1.25) 12(-5.7,-1.75) 13(-5.7,-2.25) 14(-5.7,-2.75) 15(-5.7,-3.25) 16(-5.7,-3.75) 33(5.7,-3.75) 34(5.7,-3.25) 35(5.7,-2.75) 36(5.7,-2.25) 37(5.7,-1.75) 38(5.7,-1.25) 39(5.7,-0.75) 40(5.7,-0.25) 41(5.7,0.25) 42(5.7,0.75) 43(5.7,1.25) 44(5.7,1.75) 45(5.7,2.25) 46(5.7,2.75) 47(5.7,3.25) 48(5.7,3.75)
  rrect33% 0.3x1.5 smd paste+0 mask+0: 17(-3.75,-5.7) 18(-3.25,-5.7) 19(-2.75,-5.7) 20(-2.25,-5.7) 21(-1.75,-5.7) 22(-1.25,-5.7) 23(-0.75,-5.7) 24(-0.25,-5.7) 25(0.25,-5.7) 26(0.75,-5.7) 27(1.25,-5.7) 28(1.75,-5.7) 29(2.25,-5.7) 30(2.75,-5.7) 31(3.25,-5.7) 32(3.75,-5.7) 49(3.75,5.7) 50(3.25,5.7) 51(2.75,5.7) 52(2.25,5.7) 53(1.75,5.7) 54(1.25,5.7) 55(0.75,5.7) 56(0.25,5.7) 57(-0.25,5.7) 58(-0.75,5.7) 59(-1.25,5.7) 60(-1.75,5.7) 61(-2.25,5.7) 62(-2.75,5.7) 63(-3.25,5.7) 64(-3.75,5.7)
  silkscreen extent -7.12,-5.1 5.1,5.1, body extent -6.55,-6.55 6.55,6.55, height 0.25
PowerPAK_SO-8 [mil] "Vishay PowerPAK SO-8, Body 5.3x6.0mm (max), Pitch 1.27mm, IPC Medium Density"
  rect 50x24 smd mask+2.99: 1(-109.5,75) 2(-109.5,25) 3(-109.5,-25) 4(-109.5,-75)
  rect 48x24 smd mask+2.99: 5(109.5,-75) 8(109.5,75)
  rect 48x24 smd paste-12 mask+2.99: 6(109.5,-25) 7(109.5,25)
  rect 150x154 smd paste-75 mask+2.99: 9(22.5,0)
  silkscreen extent -130,-104 59,104, body extent -121,-102 121,101, height 43
PW0016A_N [mm] "TSOP, 16-Leads, Body 5x4.4mm, Pitch 0.65mm, IPC Medium Density"
  oval 1.4x0.45 smd: 1(-2.95,2.275) 2(-2.95,1.625) 3(-2.95,0.975) 4(-2.95,0.325) 5(-2.95,-0.325) 6(-2.95,-0.975) 7(-2.95,-1.625) 8(-2.95,-2.275) 9(2.95,-2.275) 10(2.95,-1.625) 11(2.95,-0.975) 12(2.95,-0.325) 13(2.95,0.325) 14(2.95,0.975) 15(2.95,1.625) 16(2.95,2.275)
  silkscreen extent -3.5,-2.55 1.85,2.75, body extent -3.21,-2.5 3.21,2.5, height 1
RAQ0012B-MFG [mm]
  rrect33% 0.6x0.3 smd paste+0 mask+0: 1(-2.4,1.625) 2(-2.4,0.975) 3(-2.4,0.325) 4(-2.4,-0.325) 5(-2.4,-0.975) 6(-2.4,-1.625) 7(2.4,-1.625) 8(2.4,-0.975) 9(2.4,-0.325) 10(2.4,0.325) 11(2.4,0.975) 12(2.4,1.625)
  Top Layer region: -2.65,-1.125 -2.675,-1.118 -2.693,-1.1 -2.7,-1.075 -2.7,-1.075 -2.7,-0.875 -2.696,-0.856 -2.685,-0.84 -2.669,-0.829 -2.65,-0.825 -2.65,-0.825 -2.45,-0.825 -2.431,-0.821 -2.415,-0.81 -2.404,-0.794 -2.4,-0.775 -2.4,-0.775 -2.4,-0.525 -2.404,-0.506 -2.415,-0.49 -2.431,-0.479 -2.45,-0.475 -2.45,-0.475 -2.65,-0.475 -2.675,-0.468 -2.693,-0.45 -2.7,-0.425 -2.7,-0.425 -2.7,-0.225 -2.696,-0.206 -2.685,-0.19 -2.669,-0.179 -2.65,-0.175 -2.65,-0.175 -2.45,-0.175 -2.431,-0.171 -2.415,-0.16 -2.404,-0.144 -2.4,-0.125 -2.4,-0.125 -2.4,0.125 -2.404,0.144 -2.415,0.16 -2.431,0.171 -2.45,0.175 -2.45,0.175 -2.65,0.175 -2.675,0.182 -2.693,0.2 -2.7,0.225 -2.7,0.225 -2.7,0.425 -2.693,0.45 -2.675,0.468 -2.65,0.475 -2.65,0.475 -2.15,0.475 -2.131,0.471 -2.115,0.46 -2.104,0.444 -2.1,0.425 -2.1,0.425 -2.1,-1.075 -2.104,-1.094 -2.115,-1.11 -2.131,-1.121 -2.15,-1.125 -2.15,-1.125
  Top Layer region: 2.65,-0.475 2.675,-0.468 2.693,-0.45 2.7,-0.425 2.7,-0.425 2.7,-0.225 2.696,-0.206 2.685,-0.19 2.669,-0.179 2.65,-0.175 2.65,-0.175 2.45,-0.175 2.431,-0.171 2.415,-0.16 2.404,-0.144 2.4,-0.125 2.4,-0.125 2.4,0.125 2.404,0.144 2.415,0.16 2.431,0.171 2.45,0.175 2.45,0.175 2.65,0.175 2.675,0.182 2.693,0.2 2.7,0.225 2.7,0.225 2.7,0.425 2.696,0.444 2.685,0.46 2.669,0.471 2.65,0.475 2.65,0.475 2.45,0.475 2.431,0.479 2.415,0.49 2.404,0.506 2.4,0.525 2.4,0.525 2.4,0.775 2.404,0.794 2.415,0.81 2.431,0.821 2.45,0.825 2.45,0.825 2.65,0.825 2.669,0.829 2.685,0.84 2.696,0.856 2.7,0.875 2.7,0.875 2.7,1.075 2.693,1.1 2.675,1.118 2.65,1.125 2.65,1.125 2.15,1.125 2.131,1.121 2.115,1.11 2.104,1.094 2.1,1.075 2.1,1.075 2.1,-0.425 2.104,-0.444 2.115,-0.46 2.131,-0.471 2.15,-0.475 2.15,-0.475
  silkscreen extent -3.37,-2.05 1.73,2.55, body extent -2.8,-2.15 2.8,2.15, height 0.25
Samtec_FTSH-105-01-x-DV-K [mm] "Header(Shrouded), 1.27mm, 5x2, SMT"
  rect 2.79x0.74 smd: 1(-2.035,2.54) 2(2.035,2.54) 3(-2.035,1.27) 4(2.035,1.27) 5(-2.035,0) 6(2.035,0) 7(-2.035,-1.27) 8(2.035,-1.27) 9(-2.035,-2.54) 10(2.035,-2.54)
  silkscreen extent -3.73,-3.48 3.73,3.48, body extent -2.92,-3.18 2.92,3.17, height 6.13
Samtec_TSW-102-08-x-S [mm] "Header, 2.54mm, 2x1, TH"
  rrect50% 1.53x1.53 hole 1.02: 1(-1.27,0)
  round 1.53 hole 1.02: 2(1.27,0)
  silkscreen extent -2.67,-1.27 2.54,1.7, body extent -2.67,-1.27 2.54,1.27, height 8.38
SMA_Bi [mm] "SMD, 2-Leads, Body 4.275x2.575mm"
  rect 1.4x1.64 smd: 1(-2.015,0) 2(2.015,0)
  silkscreen extent -2.3,-1.45 2.3,1.45, body extent -2.52,-1.45 2.52,1.45, height 2.65
SMB [mil] "Molded Diode, 2-Leads, Body 5.4x3.6mm, IPC Medium Density, based on OnSemi component dimensions"
  rect 85x107.99 smd: 1(-87.01,0) 2(87.01,0)
  silkscreen extent -155,-82 125,82, body extent -106,-71 106,71, height 91
SMB-Bi [mil] "Molded Diode, 2-Leads, Body 5.4x3.6mm, IPC Medium Density, based on OnSemi component dimensions"
  rect 85x107.99 smd: 1(-87.01,0) 2(87.01,0)
  silkscreen extent -125,-79 125,79, body extent -104,-73 104,73, height 89
SMC [mil] "Molded Diode, 2-Leads, Body 6.9x5.8mm, IPC Medium Density, based on OnSemi component dimensions and land patterns"
  rect 110x150 smd: 1(-140.49,0) 2(140.49,0)
  silkscreen extent -221,-123 189,124, body extent -156,-116 156,116, height 91
SOD-123 [mm] "On Semi recommended land pattern"
  rect 0.915x1.22 smd: 1(-1.637,0) 2(1.637,0)
  silkscreen extent -2.74,-1.17 2.03,1.17, body extent -1.93,-0.9 1.93,0.9, height 1.35
SOD-323 [mm] "NXP recommended land pattern"
  rect 0.6x0.6 smd paste-0.05: 1(-1.1,0) 2(1.1,0)
  silkscreen extent -2.06,-0.86 1.53,0.86, body extent -1.3,-0.67 1.3,0.68, height 1.1
SOD-323F [mm] "NXP recommended land pattern"
  rect 0.6x0.6 smd paste-0.05: 1(-1.1,0) 2(1.1,0)
  silkscreen extent -2.06,-0.86 1.53,0.86, body extent -1.35,-0.67 1.35,0.68, height 0.79
SOD-523 [mm] "NXP Semiconductor recommended land pattern, nominal STEP model"
  rect 0.8x0.6 smd paste-0.05: 1(-0.55,0) 2(0.55,0)
  silkscreen extent -1.65,-0.66 1.2,0.66, body extent -0.8,-0.4 0.8,0.4, height 0.72
SOT-23 [mm] "SOT23, 3-Leads, Body 2.9x1.3mm, Pitch 0.95mm, Lead Span 2.5mm, IPC Medium Density"
  rrect50% 1x0.6 smd: 1(-1.2,0.95) 2(-1.2,-0.95) 3(1.2,0)
  silkscreen extent -1.63,-1.5 0.7,1.5, body extent -1.16,-1.45 1.21,1.45, height 1
SOT-223 [mm] "SOT223/SC73, 4-Leads, Body 6.5x3.5mm, Pitch 2.3mm, Lead Span 7mm, IPC Medium Density"
  rrect10% 2.4x1 smd: 1(-2.9,2.3) 2(-2.9,0) 3(-2.9,-2.3)
  rrect4% 2.4x3.3 smd: 4(2.9,0)
  silkscreen extent -3.32,-3.35 1.4,3.35, body extent -3.5,-3.25 3.5,3.25, height 1.62
SOT-323 [mm] "Diodes Inc recommended land pattern.  2016-02-24"
  rrect21% 0.6x0.47 smd: 1(-0.95,0.65) 2(-0.95,-0.65) 3(0.95,0)
  silkscreen extent -1.14,-1.22 0.77,1.22, body extent -1.13,-1.13 1.12,1.12, height 1.13
SULLINS_PPPC041LGBN-RC [mm] "Sullins"
  rect 1.7x1.7 hole 1.016: 1(3.81,5.5)
  round 1.7 hole 1.016: 2(1.27,5.5) 3(-1.27,5.5) 4(-3.81,5.5)
  silkscreen extent -5.33,-4.6 5.33,4.1, body extent -5.33,-4.6 5.33,5.7, height 2.56
Sullins_xxC04SAAN [mm] "Header, 2.54 mm, 4x1, TH"
  rect 1.55x1.55 hole 1.016: 1(-3.81,0)
  round 1.55 hole 1.016: 2(-1.27,0) 3(1.27,0) 4(3.81,0)
  silkscreen extent -5.08,-1.27 5.08,1.6, body extent -5.08,-1.27 5.08,1.27, height 8.38
SW_416131160802 [mm] "SMD, 4-Leads, Body 5.6x3.58mm, Pitch 1.27mm"
  rect 1.27x0.76 smd: 1(-3.81,0.635) 2(-3.81,-0.635) 3(3.81,-0.635) 4(3.81,0.635)
  silkscreen extent -2.8,-1.79 2.8,2.1, body extent -4,-1.79 4,1.79, height 2.1
SW_RS-032G05A3-SM [mm] "SMT, 2-Leads, Body 6x3.5mm, Pin Spacing 8mm"
  rect 2x2 smd: 1(-4,0) 2(4,0)
  silkscreen extent -3,-1.75 3,1.75, body extent -4,-1.75 4,1.75, height 4.3
TP_SM_1MM [mm] "1mm Test Point, SMT"
  round 1 smd paste-0.5: 1(0,0)
TSW-103-07-G-D [mm] "Samtec 100mil, 2x3, 230 mil above insulator"
  rect 1.65x1.65 hole 1.016: 1(-2.54,-1.27)
  round 1.65 hole 1.016: 2(-2.54,1.27) 3(0,-1.27) 4(0,1.27) 5(2.54,-1.27) 6(2.54,1.27)
  silkscreen extent -4.83,-2.54 3.81,2.54, body extent -3.81,-2.54 3.81,2.54, height 8.38
TSW-120-07-G-S [mm] "Samtec 100mil, 1x20, 230 mil above insulator"
  rrect6% 1.65x1.65 hole 1.016: 1(-24.13,0)
  round 1.65 hole 1.016: 2(-21.59,0) 3(-19.05,0) 4(-16.51,0) 5(-13.97,0) 6(-11.43,0) 7(-8.89,0) 8(-6.35,0) 9(-3.81,0) 10(-1.27,0) 11(1.27,0) 12(3.81,0) 13(6.35,0) 14(8.89,0) 15(11.43,0) 16(13.97,0) 17(16.51,0) 18(19.05,0) 19(21.59,0) 20(24.13,0)
  silkscreen extent -25.4,-1.27 25.4,1.65, body extent -25.4,-1.27 25.4,1.27, height 8.38
WE-MAPI_3015 [mm] "SMD, 2-Leads, Body 3x3mm"
  rect 1.3x3.4 smd: 1(-1.05,0) 2(1.05,0)
  silkscreen extent -0.12,-1.7 0.12,1.7, body extent -1.6,-1.6 1.6,1.6, height 1.5
WE-PD_7345 [mm] "SMD Inductor, 2-Leads, Body 7,3x7,3mm"
  rect 1.6x2.2 smd: 1(-3.2,0) 2(3.2,0)
  silkscreen extent -3.65,-3.68 3.61,3.6, body extent -3.65,-3.68 3.65,3.6, height 4.49
WE-PMCI_0805_L2W1.25H1 [mm] "Power Molded Chip Inductor, body 2x1.25mm"
  rect 0.7x1.45 smd: 1(-0.75,0) 2(0.75,0)
  body extent -1,-0.62 1,0.63, height 1
WE-XHMI_6060 [mm] "SMD, 2-Leads, Body 6.65x6.45mm"
  rrect7% 1.45x5.5 smd: 1(-2,0) 2(2,0)
  body extent -3.22,-3.32 3.22,3.32, height 5.78
WEEE_Minimum [mil] "WEEElie bin"
  silkscreen extent -95,-172 99,104

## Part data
D10 D2 D3 D6 D9 D22 D32 D33 D35: library part CMP-0028450-2, "Diode, Schottky, 100 V, 0.15 A, SOD-123", Manufacturer="Diodes Inc.", Value1=0.15A, Value2=0.6V
R5 R4 R305: library part CMP-0021991-4, "RES, 100, 1%, 0.1 W, AEC-Q200 Grade 0, 0603", Manufacturer=Vishay-Dale, Power_W=100mW, Supplier Part Number 1=541-100HCT-ND, TempCo="100 ppm/C", Tolerance_%=1%, Value2=0.1W, Value_Code=100R, ValueDisplayed=100
C1 C4 C5 C17 C18 C19 C20 C59 C61 C63 C72 C73 C77 C90 C92 C94 C97 C99 C100 C102 C104 C107 C109 C139: library part CMP-0007334-3, "CAP, CERM, 0.1 uF, 16 V, +/- 10%, X5R, 0603", Cap_Case=0603, Manufacturer=MuRata, Supplier Part Number 1=GRM188R61C104KA01D-ND, TempCo=X5R, Tolerance_%=10%, Value1=Unknown, Value2=16V, ValueDisplayed=0.1uF
C2 C60 C62 C91 C93 C95 C96 C98 C101 C103 C105 C106 C108: library part CMP-0081458-1, "CAP, CERM, 1 µF, 16 V,+/- 20%, X5R, 0603", Cap_Case=0603, Manufacturer="Yageo America", TempCo=X5R, Tolerance_%=20%, Value2=16V, ValueDisplayed=1µF
C3: library part CMP-0007334-3, "CAP, CERM, 0.1 uF, 16 V, +/- 10%, X5R, 0603", Cap_Case=0603, Manufacturer=MuRata, PartNumber=GRM188R61C104KA01D, Supplier Part Number 1=GRM188R61C104KA01D-ND, TempCo=X5R, Tolerance_%=10%, Value1=Unknown, Value2=16V, ValueDisplayed=0.1uF
C6: library part CMP-0081458-1, "CAP, CERM, 1 µF, 16 V,+/- 20%, X5R, 0603", Cap_Case=0603, Manufacturer="Yageo America", PartNumber=CC0603MRX5R7BB105, TempCo=X5R, Tolerance_%=20%, Value2=16V, ValueDisplayed=1µF
C7 C74 C75 C80 C81 C114 C130: library part CMP-0007136-1, "CAP, CERM, 1 uF, 16 V, +/- 10%, X7R, AEC-Q200 Grade 1, 0603", Cap_Case=0603, Manufacturer=MuRata, Supplier Part Number 1=490-5241-6-ND, TempCo=X7R, Tolerance_%=10%, Value1=Unknown, Value2=16V, ValueDisplayed=1uF
C8 C9 C10 C28 C29 C30 C31 C32 C33 C34 C35 C36 C37 C38 C39 C40 C41 C42 C43 C44 C45 C46 C47 C48 C49 C50 C51 C52 C53 C54 C55 C57 C58 C140 C148 C301: library part CMP-0007434-4, "CAP, CERM, 0.1 uF, 50 V, +/- 10%, X7R, 0603", Cap_Case=0603, Manufacturer=MuRata, Supplier Part Number 1=490-1519-1-ND, TempCo=X7R, Tolerance_%=10%, Value1=Unknown, Value2=50V, ValueDisplayed=0.1uF
C11 C135 C136: library part CMP-0007499-1, "CAP, CERM, 2.2 uF, 16 V, +/- 10%, X7R, 0603", Cap_Case=0603, Manufacturer=MuRata, Supplier Part Number 1=81-GRM188Z71C225KE3D, TempCo=X7R, Tolerance_%=10%, Value1=Unknown, Value2=16V, ValueDisplayed=2.2uF
C12: library part CMP-0007138-2, "CAP, CERM, 0.47 uF, 16 V, +/- 10%, X7R, AEC-Q200 Grade 1, 0603", Cap_Case=0603, Manufacturer=MuRata, Supplier Part Number 1=490-4775-1-ND, TempCo=X7R, Tolerance_%=10%, Value1=Unknown, Value2=16V, ValueDisplayed=0.47uF
C13: library part CMP-0006683-1, "CAP, CERM, 2200 pF, 50 V, +/- 10%, X7R, 0402", Cap_Case=0402, Manufacturer=MuRata, Supplier Part Number 1=490-1305-1-ND, TempCo=X7R, Tolerance_%=10%, Value1=Unknown, Value2=50V, ValueDisplayed=2200pF
C14: library part CMP-0006977-1, "CAP, CERM, 0.01 uF, 100 V, +/- 10%, X7R, 0603", Cap_Case=0603, Manufacturer=Kemet, Supplier Part Number 1=399-5347-1-ND, TempCo=X7R, Tolerance_%=10%, Value1=Unknown, Value2=100V, ValueDisplayed=0.01uF
C15 C16 C25 C26: library part CMP-0006439-2, "CAP, CERM, 22 pF, 50 V, +/- 5%, C0G/NP0, 0402", Cap_Case=0402, Manufacturer=MuRata, Supplier Part Number 1=81-GRM1555C1H220JA1D, TempCo=C0G/NP0, Tolerance_%=5%, Value1=Unknown, Value2=50V, ValueDisplayed=22pF
C21 C22 C56 C150 C159 C160 C161 C162 C163 C164 C165 C166 C167 C168 C169 C170 C171 C172: library part CMP-0009758-1, "CAP, CERM, 470 pF, 16 V, +/- 10%, X7R, 0201", Cap_Case=0201, Manufacturer=MuRata, Supplier Part Number 1=GRM033R71C471KA01D-ND, TempCo=X7R, Tolerance_%=10%, Value1=Unknown, Value2=16V, ValueDisplayed=470pF
C23: library part CMP-0079154-1, "CAP, CERM, 1 µF, 16 V,+/- 10%, X7R, AEC-Q200 Grade 1, 0603", Cap_Case=0603, Manufacturer=MuRata, Supplier Part Number 1=490-12657-1-ND, TempCo=X7R, Tolerance_%=10%, Value2=16V, ValueDisplayed=1µF
C24: library part CMP-0007006-5, "CAP, CERM, 1 uF, 25 V, +/- 10%, X5R, 0603", Cap_Case=0603, Manufacturer=TDK, Supplier Part Number 1=445-5146-1-ND, TempCo=X5R, Tolerance_%=10%, Value1=Unknown, Value2=25V, ValueDisplayed=NC
C27: library part CMP-0006678-2, "CAP, CERM, 1500 pF, 50 V, +/- 10%, X7R, 0402", Cap_Case=0402, Manufacturer=MuRata, Supplier Part Number 1=490-3245-1-ND, TempCo=X7R, Tolerance_%=10%, Value1=Unknown, Value2=50V, ValueDisplayed=1500pF
C64 C70: library part CMP-0008971-2, "CAP, CERM, 2.2 uF, 100 V, +/- 10%, X7R, 1206_190", Cap_Case=1206, Manufacturer=MuRata, Supplier Part Number 1=490-7209-1-ND, TempCo=X7R, Tolerance_%=10%, Value1=Unknown, Value2=100V, ValueDisplayed=2.2uF
C65 C76 C78 C84 C87 C89 C112 C137: library part CMP-0007237-4, "CAP, CERM, 100 pF, 100 V, +/- 5%, C0G/NP0, 0603", Cap_Case=0603, Manufacturer=MuRata, Supplier Part Number 1=490-1351-1-ND, TempCo=C0G/NP0, Tolerance_%=5%, Value1=Unknown, Value2=100V, ValueDisplayed=100pF
C66: library part CMP-0008342-1, "CAP, CERM, 2.2 uF, 25 V, +/- 10%, X7R, 0805", Cap_Case=0805, Manufacturer=MuRata, Supplier Part Number 1=490-3331-1-ND, TempCo=X7R, Tolerance_%=10%, Value1="0.005 ohm", Value2=25V, ValueDisplayed=2.2uF
C67 C71: library part CMP-0064934-1, "CAP, CERM, 2.2 uF, 16 V,+/- 10%, X7R, 0603", Cap_Case=0603, Manufacturer="Taiyo Yuden", Supplier Part Number 1=587-4864-1-ND, TempCo=X7R, Tolerance_%=10%, Value1=Unknown, Value2=16V, ValueDisplayed=2.2uF
C68: "CAP, CERM, 0.1 µF, 50 V,+/- 10%, X7R, 0603", Cap_Case=0603, Manufacturer=MuRata, Supplier Part Number 1=490-1519-1-ND, TempCo=X7R, Tolerance_%=10, Value2=50V, ValueDisplayed=0.1µF
C69 C79: library part CMP-0007444-2, "CAP, CERM, 0.022 uF, 50 V, +/- 10%, X7R, 0603", Cap_Case=0603, Manufacturer=MuRata, Supplier Part Number 1=490-1517-1-ND, TempCo=X7R, Tolerance_%=10%, Value1=Unknown, Value2=50V, ValueDisplayed=0.022uF
C82 C83: library part CMP-0008710-1, "CAP, CERM, 1 uF, 100 V, +/- 10%, X7R, 1206", Cap_Case=1206_180, Manufacturer=TDK, Supplier Part Number 1=445-4467-1-ND, TempCo=X7R, Tolerance_%=10%, Value1="0.004575 ohm", Value2=100V, ValueDisplayed=1uF
C85 C86 C88: library part CMP-0007220-3, "CAP, CERM, 47 pF, 50 V, +/- 5%, C0G/NP0, 0603", Cap_Case=0603, Manufacturer=MuRata, Supplier Part Number 1=490-1419-1-ND, TempCo=C0G/NP0, Tolerance_%=5%, Value1=Unknown, Value2=50V, ValueDisplayed=47pF
C110 C111 C113: library part CMP-0008585-2, "CAP, CERM, 0.1 uF, 200 V, +/- 10%, X7R, 1206", Cap_Case=1206, Manufacturer=Kemet, Supplier Part Number 1=399-8139-1-ND, TempCo=X7R, Tolerance_%=10%, Value1=Unknown, Value2=200V, ValueDisplayed=0.1uF
C115 C124 C125 C141 C142 C152 C153: library part CMP-0006357-1, "CAP, CERM, 2200 pF, 50 V, +/- 10%, X7R, AEC-Q200 Grade 1, 0402", Cap_Case=0402, Manufacturer=MuRata, Supplier Part Number 1=490-4914-1-ND, TempCo=X7R, Tolerance_%=10%, Value1=Unknown, Value2=50V, ValueDisplayed=2200pF
C116 C121: library part CMP-0081058-1, "CAP, CERM, 1 µF, 200 V,+/- 10%, X7R, 1812", Cap_Case=1812_280, Manufacturer=AVX, Supplier Part Number 1=478-10705-1-ND, TempCo=X7R, Tolerance_%=10%, Value2=200V, ValueDisplayed=1µF
C117: library part CMP-0006357-2, "CAP, CERM, 2200 pF, 50 V, +/- 10%, X7R, AEC-Q200 Grade 1, 0402", Cap_Case=0402, Manufacturer=MuRata, Supplier Part Number 1=490-4914-1-ND, TempCo=X7R, Tolerance_%=10%, Value1=Unknown, Value2=50V, ValueDisplayed=2200pF
C118 C119 C126 C127 C143 C144 C154 C155: library part CMP-0008377-2, "CAP, CERM, 22 uF, 10 V, +/- 20%, X7R, 0805", Cap_Case=0805, Manufacturer=MuRata, Supplier Part Number 1=81-GRM21BZ71A226ME5L, TempCo=X7R, Tolerance_%=20%, Value1=Unknown, Value2=10V, ValueDisplayed=22uF
C120: library part CMP-0009089-1, "CAP, CERM, 0.068 uF, 200 V, +/- 5%, X7R, 1210", Cap_Case=1210, Manufacturer=Kemet, Supplier Part Number 1=C1210C683J2RACTU-ND, TempCo=X7R, Tolerance_%=5%, Value1=Unknown, Value2=200V, ValueDisplayed=0.068uF
C122 C123: library part CMP-0064919-1, "CAP, CERM, 2.2 uF, 200 V,+/- 10%, X7R, 2220", Cap_Case=2220, Manufacturer="Knowles Capacitors", PartNumber=2220Y6300105KXTWS2, Supplier Part Number 1=1608-1181-1-ND, TempCo=X7R, Tolerance_%=10%, Value1=Unknown, Value2=630V, ValueDisplayed=2.2uF
C128: library part CMP-0086499-1, "Cap Ceramic 0.1uF 200V X7R 10% SMD 1206", Manufacturer="TDK Corporation", PartNumber=CGA5H2X8R2A104K115AA, TempCo=15%, Tolerance_%=10%
C129: library part CMP-0093400-1, "10 µF 160 V Aluminum Electrolytic Capacitors Radial, Can - SMD - 3000 Hrs @ 105°C", Digikey Part Number=PCE3421CT-ND, Leakage Current=106uA, Manufacturer="Panasonic Electronic Components", Mouser Part Number=667-EEV-EB2C100Q, Operating Temperature Range="-25°C to +105°C", Tolerance_%=20%, ValueDisplayed=10uF
C131: library part CMP-0007224-1, "CAP, CERM, 56 pF, 50 V, +/- 5%, C0G/NP0, 0603", Cap_Case=0603, Manufacturer=MuRata, Supplier Part Number 1=490-1421-1-ND, TempCo=C0G/NP0, Tolerance_%=5%, Value1=Unknown, Value2=50V, ValueDisplayed=NC
C132 C133 C134: library part CMP-0008334-1, "CAP, CERM, 4.7 uF, 16 V, +/- 10%, X7R, 0805", Cap_Case=0805, Manufacturer=MuRata, Supplier Part Number 1=490-4522-1-ND, TempCo=X7R, Tolerance_%=10%, Value1="0.006 ohm", Value2=16V, ValueDisplayed=4.7uF
C138: library part CMP-0007122-5, "CAP, CERM, 10 uF, 16 V, +/- 20%, X5R, 0603", Cap_Case=0603, Manufacturer="Taiyo Yuden", Supplier Part Number 1=587-3238-1-ND, TempCo=X5R, Tolerance_%=20%, Value1=Unknown, Value2=16V, ValueDisplayed=10uF
C145 C146: library part CMP-0085950-1, "CAP, CERM, 10 µF, 50 V,+/- 10%, X7R, AEC-Q200 Grade 1, 1206", Cap_Case=1206, Manufacturer=TDK, TempCo=X7R, Tolerance_%=10%, Value2=50V, ValueDisplayed=10µF
C147 C151 C158: library part CMP-0079602-1, "CAP, CERM, 0.1 µF, 50 V,+/- 10%, X7R, AEC-Q200 Grade 1, 0603", Cap_Case=0603, Manufacturer=Kemet, Supplier Part Number 1=399-6856-1-ND, TempCo=X7R, Tolerance_%=10%, Value2=50V, ValueDisplayed=0.1µF
C149: library part CMP-0007392-4, "CAP, CERM, 0.033 uF, 16 V, +/- 10%, X7R, 0603", Cap_Case=0603, Manufacturer=MuRata, Supplier Part Number 1=490-1528-1-ND, TempCo=X7R, Tolerance_%=10%, Value1=Unknown, Value2=16V, ValueDisplayed=0.033uF
C156 C157: library part CMP-0008667-2, "CAP, CERM, 22 uF, 35 V, +/- 20%, X5R, 1206", Cap_Case=1206_180, Manufacturer=TDK, Supplier Part Number 1=445-8045-1-ND, TempCo=X5R, Tolerance_%=20%, Value1="0.002398 ohm", Value2=35V, ValueDisplayed=22uF
CP1 DSG LD TP1 TP2 TP3 TP4 TP5 TP6 TP7 TP8 TP10 TP11 TP13 TP14 TP15 TP16 TP18 TP21 TP22 TP23 TP25 TP26 TP30: library part CMP-0003825-1, "1mm Test Point, SMT", Manufacturer=Any, PartNumber=TP_SM_1MM
D1: library part CMP-0077073-2, "Diode, Schottky, 20 V, 2 A, SOD-323F", Manufacturer=Nexperia, Value1=2A, Value2=0.525V
D4 D7: library part CMP-0028447-2, "Diode, Schottky, 30 V, 0.2 A, SOD-323", Manufacturer="Diodes Inc.", Value1=0.2A, Value2=1V
D5 D10: library part CMP-0028894-3, "Diode, Schottky, 100 V, 0.2 A, SOD-523", Manufacturer=STMicroelectronics, Value1=0.2A, Value2=1V
D8: "Diode, Schottky, 30 V, 0.2 A, SOD-323", Manufacturer="Diodes Inc.", Supplier Part Number 1=BAT42WSDICT-ND, Value1=0.2A, Value2=1V
D11 D12 D14 D18: library part CMP-0005782-3, "Diode, Zener, 3.6 V, 500 mW, SOD-123", Manufacturer="ON Semiconductor", Power_W=500mW, Value1=0.5W
D13 D21 D23 D24 D29: library part CMP-0005754-4, "Diode, Zener, 16 V, 500 mW, SOD-123", Manufacturer="Diodes Inc.", Power_W=500mW, Value1=0.5W
D15 D42: library part CMP-0085025-1, "Diode, TVS, Bi, 60 V, 96.8 Vc, 400 W, 4.1 A, SMA (non-polarized)", Manufacturer=Littelfuse, Value1=96.8V
D16 D19 D20 D34: library part CMP-0005738-1, "Diode, Zener, 75V, 500 mW, AEC-Q101, SOD-123", Manufacturer="ON Semiconductor", PartNumber=MMSZ5263BT1G, Power_W=500mW, Supplier Part Number 1=MMSZ5263BT1GOSCT-ND, Value1=0.5W
D17: library part CMP-0028868-1, "Diode, Schottky, 20 V, 0.5 A, SOD-323F", Manufacturer=Panasonic, Supplier Part Number 1=DB2J20900LCT-ND, Value1=0.5A, Value2=0.5V
D25: library part CMP-0005865-2, "Diode, Zener, 5.1 V, 200 mW, SOD-323", Manufacturer="Diodes Inc.", Power_W=200mW, Value1=0.2W
D26 D30 D31 D36: library part CMP-0076946-1, "Diode, Schottky, 100 V, 0.25 A, SOD-323F", Manufacturer=Nexperia, Supplier Part Number 1=568-6017-1-ND, Value1=0.25A, Value2=0.85V
D27: library part CMP-0076946-1, "Diode, Schottky, 100 V, 0.25 A, SOD-323F", Manufacturer=Nexperia, PartNumber=BAT46WJ,115, Supplier Part Number 1=568-6017-1-ND, Value1=0.25A, Value2=0.85V
D28: library part CMP-0076979-1, "Diode, Switching, 100 V, 0.25 A, SOD-523", Manufacturer=Nexperia, Supplier Part Number 1=568-1603-1-ND, Value1=0.25A, Value2=1.25V
D37: library part CMP-0029041-2, "Diode, Ultrafast, 200 V, 3 A, SMC", Manufacturer=MDD, Value1=5A, Value2=0.9V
